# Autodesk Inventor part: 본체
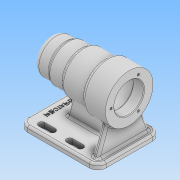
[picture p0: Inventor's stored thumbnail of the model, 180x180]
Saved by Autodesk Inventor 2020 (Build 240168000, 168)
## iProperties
Created: 2021-10
Part Number: 본체
Material: 일반
Document SubType Name: Modeling
Designer: user
Density: 1 g/cm^3
Appearance: 기본값
Author: user
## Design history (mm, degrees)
sketch "스케치1"
  geometry: L1 (0, 0)-(24, 0); L2 (24, 0)-(24, 25); L3 (24, 25)-(0, 25); L4 (0, 25)-(0, 0); L5 (24, 0)-(46, 0); L6 (46, 0)-(46, 27); L7 (46, 27)-(24, 27); L8 (24, 27)-(24, 0); L9 (46, 0)-(80, 0); L10 (80, 0)-(80, 30); L11 (80, 30)-(46, 30); L12 (46, 30)-(46, 0); L13 (80, 0)-(112, 0); L14 (112, 0)-(112, 34); L15 (112, 34)-(80, 34); L16 (80, 34)-(80, 0); 3 further points
  constraints: 32 end point, 8 parallel, 4 horizontal, 4 perpendicular
  dimensions: "d0" = 50 diameter of L3 L13; "d1" = 54 diameter of L7 L13; "d2" = 60 diameter of L11 L13; "d3" = 68 diameter of L15 L13; "d17" = 24 distance of L2.end L3.end; "d18" = 46 distance between parallel lines of L4 L12; "d19" = 80 distance between parallel lines of L4 L10; "d20" = 112 distance between parallel lines of L4 L14
revolve "회전1" sketch "스케치1" stored, may be unused: angle "d4" = 90 deg
sketch "스케치2"
  geometry: L1 (112, -34)-(112, 34) reference; L2 (112, 0)-(97, 0); L3 (97, 0)-(97, 21); L4 (97, 21)-(112, 21); L5 (112, 21)-(112, 0); L6 (97, 0)-(43, 0); L7 (43, 0)-(43, 24); L8 (43, 24)-(97, 24); L9 (97, 24)-(97, 0); L10 (43, 0)-(31, 0); L11 (31, 0)-(31, 21); L12 (31, 21)-(43, 21); L13 (43, 21)-(43, 0); L14 (31, 0)-(13, 0); L15 (13, 0)-(13, 17.5); L16 (13, 17.5)-(31, 17.5); L17 (31, 17.5)-(31, 0); L18 (13, 0)-(9, 0); L19 (9, 0)-(9, 16); L20 (9, 16)-(13, 16); L21 (13, 16)-(13, 0); L22 (9, 0)-(6, 0); L23 (6, 0)-(6, 10.5); L24 (6, 10.5)-(9, 10.5); L25 (9, 10.5)-(9, 0); 7 further points
  constraints: 48 end point, 12 parallel, 6 horizontal, 6 perpendicular, 1 midpoint, 1 point on line
  dimensions: "d5" = 42 diameter of L4 L2; "d6" = 15 distance of L3.end L4.end; "d7" = 48 diameter of L8 L2; "d9" = 21 diameter of L24 L2; "d10" = 3 distance of L23.end L24.end; "d11" = 32 diameter of L20 L2; "d12" = 4 distance of L19.end L20.end; "d13" = 35 diameter of L16 L2; "d14" = 18 distance of L15.end L16.end; "d15" = 12 distance of L11.end L12.end; "d16" = 54 distance of L7.end L8.end
revolve "회전2" sketch "스케치2" stored, may be unused: angle "d21" = 90 deg
node "작업 평면1"
sketch "스케치4"
  geometry: L1 (0, 45)-(-112, 45); L2 (-112, 45)-(-112, -45); L3 (-112, -45)-(0, -45); L4 (0, -45)-(0, 45); L5 (0, 45)-(-112, -45); L6 (-112, 45)-(0, -45); L7 (0, 25)-(0, -25) reference; 3 further points
  constraints: 12 end point, 2 midpoint, 2 parallel, 1 coincident, 1 horizontal, 1 perpendicular
  dimensions: "d23" = 112 distance of L2.end L3.end; "d24" = 90 distance of L3.end L1.start; "d25" = 56 distance from line of point (-56, 0) L7; "d26" = 45 distance from line of L3 point (0, 0)
extrude "돌출1" join sketch "스케치4" distance "d27" = 8; taper "d28" = 0 deg
sketch "스케치5"
  geometry: L1 (20, 33)-(35, 33); L2 (20, 28.5)-(35, 28.5); L3 (35, 37.5)-(20, 37.5); L4 (60, 33)-(75, 33); L5 (60, 28.5)-(75, 28.5); L6 (75, 37.5)-(60, 37.5); L7 (0, 0)-(-30.43, 0); L8 (20, -33)-(35, -33); L9 (20, -28.5)-(35, -28.5); L10 (35, -37.5)-(20, -37.5); L11 (60, -33)-(75, -33); L12 (60, -28.5)-(75, -28.5); L13 (75, -37.5)-(60, -37.5); L14 (112, -45)-(112, 45) reference; L15 (0, 45)-(0, -45) reference; A1 r 4.5 centre (20, 33) between (20, 37.5) and (20, 28.5); A2 r 4.5 centre (35, 33) between (35, 28.5) and (35, 37.5); A3 r 4.5 centre (60, 33) between (60, 37.5) and (60, 28.5); A4 r 4.5 centre (75, 33) between (75, 28.5) and (75, 37.5); A5 r 4.5 centre (20, -33) between (20, -28.5) and (20, -37.5); A6 r 4.5 centre (35, -33) between (35, -37.5) and (35, -28.5); A7 r 4.5 centre (60, -33) between (60, -28.5) and (60, -37.5); A8 r 4.5 centre (75, -33) between (75, -37.5) and (75, -28.5); 4 further points
  constraints: 34 end point, 16 point on circle, 14 symmetric about line, 8 centre point, 8 tangent, 4 point on line, 2 horizontal, 2 midpoint, 2 parallel, 4 other
  dimensions: "d29" = 9 distance between parallel lines of L2 L3; "d30" = 15 distance of L1.end L1.start; "d31" = 15 distance of L4.start L4.end; "d32" = 25 distance of L11.start L8.end; "d33" = 66 distance of point (27.5, -33) point (27.5, 33); "d81" = 20 distance from line of L15 L1.start
extrude "돌출2" cut sketch "스케치5" distance "d35" = 12; taper "d36" = 0 deg
sketch "스케치7"
  geometry: L1 (104, -4)-(27, -4); L2 (27, -4)-(27, 4); L3 (27, 4)-(104, 4); L4 (104, 4)-(104, -4); L5 (104, -4)-(27, 4); L6 (27, -4)-(104, 4); L7 (112, 45)-(0, 45) reference; L8 (112, -45)-(112, 45) reference; 3 further points
  constraints: 12 end point, 2 midpoint, 2 parallel, 1 horizontal, 1 perpendicular, 1 point on line
  dimensions: "d37" = 8 distance of L1.end L2.end; "d39" = 8 distance from line of L8 point (104, 45); "d40" = 77 distance from line of L2 point (104, 45); "d41" = 0 distance from line of point (104, 45) L4
extrude "돌출3" join sketch "스케치7" stored distance "d42" = 12; taper "d43" = 0 deg
feature "면 기울기1" dims angle "d44" = 15 deg
sketch "스케치9"
  geometry: L1 (49, 0)-(-41, 0) reference; L2 (-33, 0)-(-19.409, 37.342); L3 (4, 62)-(4, 69.814); L4 (41, 0)-(27.409, 37.342); L5 (49, -8)-(49, 0) reference; L6 (-41, 0)-(49, 0) reference; L7 (0, 0)-(0, 28.236) reference; L8 (8, 0)-(8, 28.236) reference; A1 r 34 centre (4, 62) between (-19.409, 37.342) and (0, 28.236) reference; 3 further points
  constraints: 6 end point, 2 symmetric about line, 1 point on circle, 1 point on line, 1 vertical
  dimensions: "d45" = 8 distance from line of L5 L4.start; "d46" = 110 deg angle of L1 L4
extrude "돌출4" join sketch "스케치9" distance "d47" = 8; taper "d48" = 0 deg
sketch "스케치10" dims "d49" = 52
  geometry: C1 r 10.5 at (0, 0) reference; 3 further points
  constraints: 1 coincident, 1 horizontal alignment, 2 other
hole "구멍1" sketch "스케치10" at (-26, 0) diameter "d50" = 3.242; stored, may be unused: countersink angle "d54" = 90 deg, drill point angle "d56" = 118 deg; dims "d51" = 8, "d52" = 4, "d53" = 2, "d55" = 11
fillet "모깎기1" dims "d60" = 0.3
fillet "모깎기2" dims "d61" = 3
fillet "모깎기3" dims "d62" = 3
chamfer "모따기1" distance "d63" = 1; stored, may be unused: second distance "d64" = 2, angle "d65" = 45 deg
fillet "모깎기4" dims "d66" = 8
fillet "모깎기5" dims "d67" = 12
fillet "모깎기6" dims "d68" = 3
fillet "모깎기7" dims "d69" = 3
fillet "모깎기8" dims "d70" = 3
sketch "스케치13"
  geometry: L1 (0, 33)-(0, -33) reference; 2 further points
  constraints: 1 other
  dimensions: "d78" = 12 distance from line of L1 point (12, -0.117)
fillet "모깎기11" dims "d76" = 3
fillet "모깎기12" dims "d77" = 3
feature "엠보싱1" dims "d0" = 50, "d1" = 54, "d2" = 60, "d3" = 68, "d17" = 24, "d18" = 46, "d19" = 80, "d20" = 112, "d79" = 0.5, "d80" = 0
node "솔리드1"
pattern_circular "원형 패턴1" dims angle "d58" = 360 deg
